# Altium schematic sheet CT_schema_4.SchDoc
size 294 x 169 mm
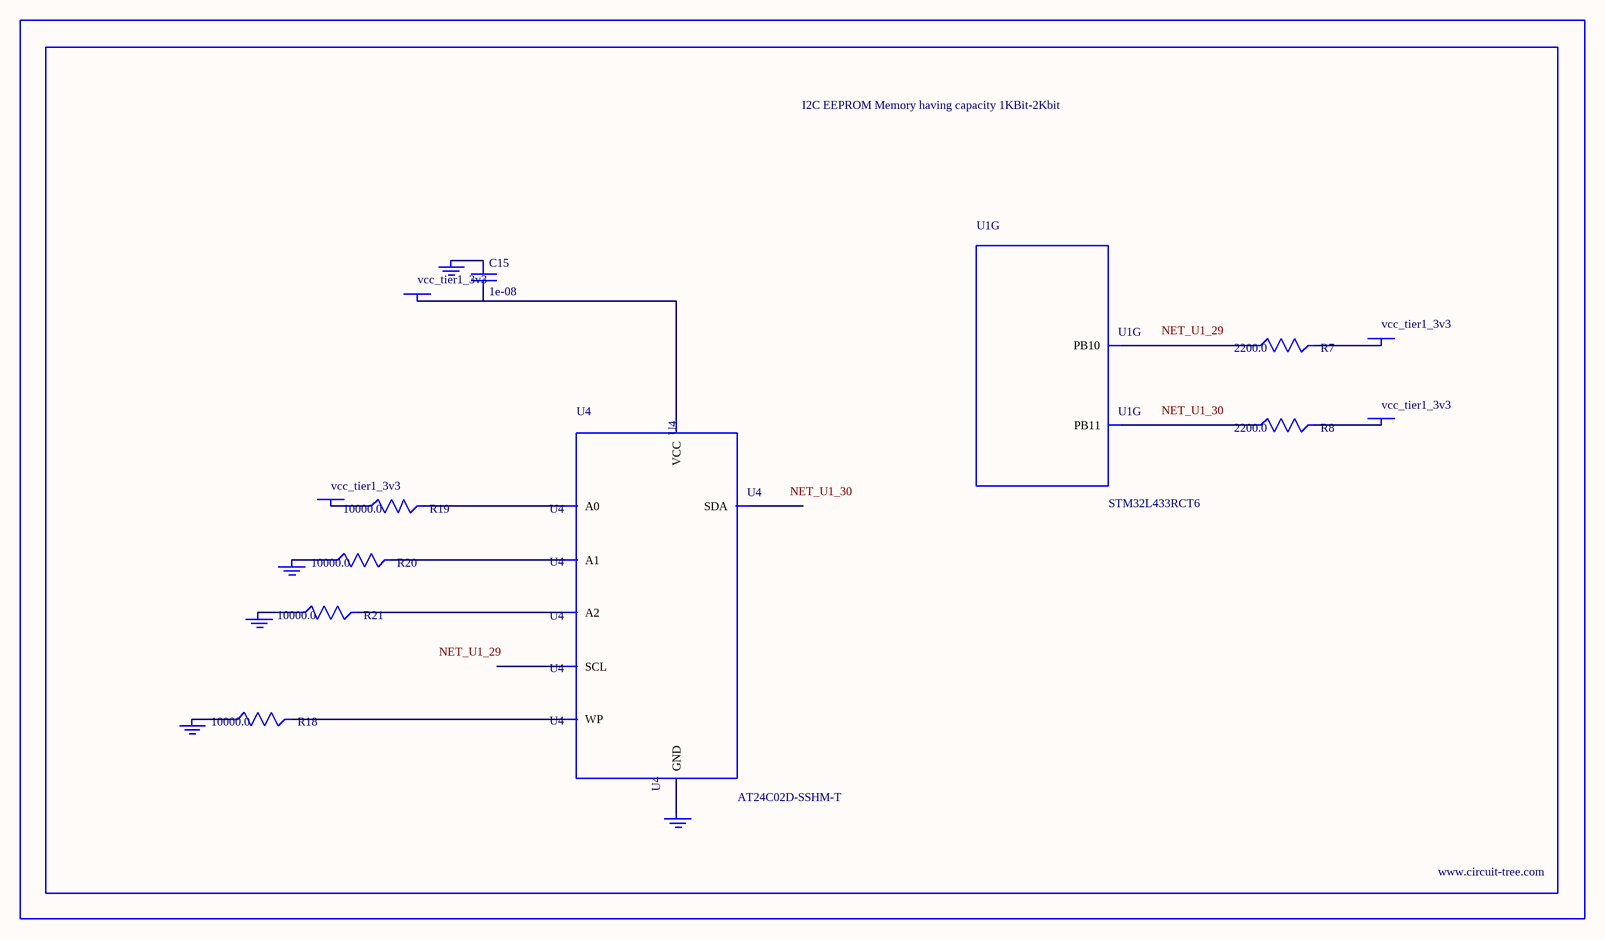
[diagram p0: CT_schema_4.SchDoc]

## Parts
BORDER3  (no value)
C15  1e-08  [C0402]
GND_INSTANCE_3_0  (no value)
GND_INSTANCE_3_1  (no value)
GND_INSTANCE_3_2  (no value)
GND_INSTANCE_3_3  (no value)
GND_INSTANCE_3_4  (no value)
POWER_INSTANCE_3_0  vcc_tier1_3v3
POWER_INSTANCE_3_1  vcc_tier1_3v3
POWER_INSTANCE_3_2  vcc_tier1_3v3
POWER_INSTANCE_3_3  vcc_tier1_3v3
R7  2200.0  [R0603]
R8  2200.0  [R0603]
R18  10000.0  [R0603]
R19  10000.0  [R0603]
R20  10000.0  [R0603]
R21  10000.0  [R0603]
U1  STM32L433RCT6  [LQFP64]  (part G of 8)
U4  AT24C02D-SSHM-T  [AT24C02D]

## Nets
NetC15_1: C15.1 GND_INSTANCE_3_3.0(GND)
NetC15_2: C15.2 POWER_INSTANCE_3_1.0(PWR) U4.8(VCC)
NetGND_INSTANCE_3_0_0: GND_INSTANCE_3_0.0(GND) R20.1
NetGND_INSTANCE_3_1_0: GND_INSTANCE_3_1.0(GND) R21.1
NetGND_INSTANCE_3_2_0: GND_INSTANCE_3_2.0(GND) R18.1
NetGND_INSTANCE_3_4_0: GND_INSTANCE_3_4.0(GND) U4.4(GND)
NetPOWER_INSTANCE_3_0_0: POWER_INSTANCE_3_0.0(PWR) R19.1
NetPOWER_INSTANCE_3_2_0: POWER_INSTANCE_3_2.0(PWR) R7.2
NetPOWER_INSTANCE_3_3_0: POWER_INSTANCE_3_3.0(PWR) R8.2
NetR7_1: R7.1 U1.29(PB10)
NetR8_1: R8.1 U1.30(PB11)
NetR18_2: R18.2 U4.7(WP)
NetR19_2: R19.2 U4.1(A0)
NetR20_2: R20.2 U4.2(A1)
NetR21_2: R21.2 U4.3(A2)

Not connected (* = marked no-connect by the designer): U4 5(SDA) 6(SCL)

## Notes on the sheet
- Labels drawn without touching a wire or pin: NET_U1_29, NET_U1_30

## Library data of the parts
BORDER3 = BORDER_PAGE3
C15 = C0402C103K3RAC
GND_INSTANCE_3_0-GND_INSTANCE_3_4 = GND
POWER_INSTANCE_3_0-POWER_INSTANCE_3_3 = PWR
R7 R8 = RC0603JR-072K2L
R18-R21 = RC0603JR-0710KL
